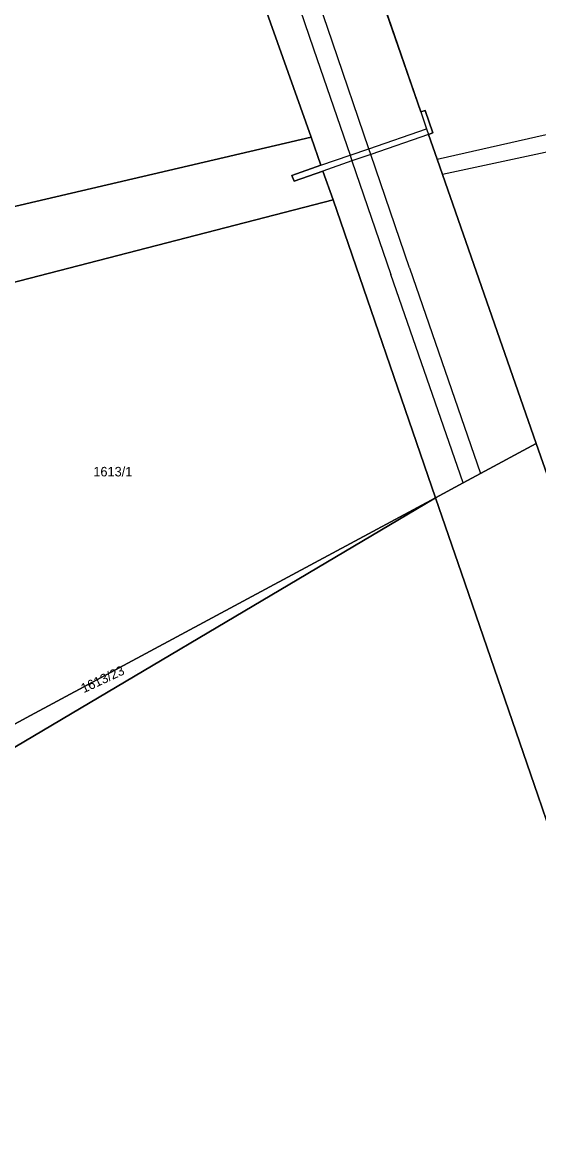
# Model space of a CAD drawing. Extents: x -263943 to -261149, y -1236934 to -1230686.
# Drawn here: x -262663.8 to -262555.5, y -1236658.9 to -1236424.4 of the extents above; entities that cross this region are included whole.
import ezdxf

# ---------------------------------------------------------------- set-up
doc = ezdxf.new("R2010")
doc.units = 0
for name, color, linetype in [('body_kn', 7, 'Continuous'), ('kladpar_druhypozemkov', 7, 'Continuous'), ('kladpar_hranice', 7, 'Continuous'), ('kladpar_parcelnecisla', 7, 'Continuous'), ('kladpar_plochy', 7, 'Continuous'), ('zappar_hrandruhpozemk', 7, 'Continuous'), ('zuob_linie', 7, 'Continuous'), ('zuob_plochy', 7, 'Continuous')]:
    doc.layers.add(name, color=color, linetype=linetype)

msp = doc.modelspace()

# ---------------------------------------------------------------- linework, layer by layer
at = {"layer": 'body_kn'}
for p, q in [((-262602.74, -1236429.99), (-262602.74, -1236429.99)), ((-262598.75, -1236428.57), (-262598.75, -1236428.57)), ((-262580.27, -1236443.22), (-262580.27, -1236443.22)), ((-262580.27, -1236443.22), (-262580.27, -1236443.22)), ((-262579.34, -1236442.89), (-262579.34, -1236442.89)), ((-262603.25, -1236448.52), (-262603.25, -1236448.52)), ((-262579.04, -1236446.74), (-262579.04, -1236446.74)), ((-262579.04, -1236446.74), (-262579.04, -1236446.74)), ((-262578.63, -1236447.93), (-262578.63, -1236447.93)), ((-262578.63, -1236447.93), (-262578.63, -1236447.93)), ((-262577.75, -1236447.63), (-262577.75, -1236447.63)), ((-262591.14, -1236450.94), (-262591.14, -1236450.94)), ((-262595.1, -1236452.31), (-262595.1, -1236452.31)), ((-262594.69, -1236453.5), (-262594.69, -1236453.5)), ((-262590.73, -1236452.13), (-262590.73, -1236452.13)), ((-262576.84, -1236453.1), (-262576.84, -1236453.1)), ((-262576.84, -1236453.1), (-262576.84, -1236453.1)), ((-262601.19, -1236454.42), (-262601.19, -1236454.42)), ((-262601.19, -1236454.42), (-262601.19, -1236454.42)), ((-262600.77, -1236455.61), (-262600.77, -1236455.61)), ((-262607.27, -1236456.53), (-262607.27, -1236456.53)), ((-262606.85, -1236457.72), (-262606.85, -1236457.72)), ((-262575.7, -1236456.35), (-262575.7, -1236456.35)), ((-262598.66, -1236461.66), (-262598.66, -1236461.66)), ((-262582.63, -1236475.95), (-262582.63, -1236475.95)), ((-262586.54, -1236477.29), (-262586.54, -1236477.29)), ((-262556.06, -1236512.78), (-262556.06, -1236512.78)), ((-262556.06, -1236512.78), (-262556.06, -1236512.78)), ((-262567.72, -1236519.05), (-262567.72, -1236519.05)), ((-262571.34, -1236520.99), (-262571.34, -1236520.99)), ((-262571.34, -1236520.99), (-262571.34, -1236520.99)), ((-262577.19, -1236524.13), (-262577.19, -1236524.13)), ((-262571.74, -1236539.97), (-262571.74, -1236539.97)), ((-262611.91, -1236542.78), (-262611.91, -1236542.78)), ((-262611.91, -1236542.78), (-262611.91, -1236542.78)), ((-262662.14, -1236569.78), (-262662.14, -1236569.78)), ((-262555.72, -1236586.53), (-262555.72, -1236586.53))]:
    msp.add_line(p, q, dxfattribs=at)
at = {"layer": 'kladpar_druhypozemkov'}
for p, q in [((-262644.48, -1236517.35), (-262644.48, -1236517.35)), ((-262640.16, -1236560.26), (-262640.16, -1236560.26))]:
    msp.add_line(p, q, dxfattribs=at)
at = {"layer": 'kladpar_hranice'}
msp.add_line((-262555.72, -1236586.53), (-262539.77, -1236633.03), dxfattribs=at)
for points in [[(-262642.35, -1236338.08), (-262623.64, -1236391.05), (-262603.25, -1236448.52), (-262686.84, -1236468.05), (-262780.06, -1236489.47), (-262796.24, -1236388.03), (-262804.88, -1236333.48), (-262777.92, -1236327.98), (-262779.92, -1236319.26), (-262779.84, -1236319.6), (-262664.48, -1236274.71), (-262659.55, -1236288.77), (-262642.35, -1236338.08)], [(-262601.19, -1236454.42), (-262607.27, -1236456.53), (-262606.85, -1236457.72), (-262600.77, -1236455.61), (-262598.66, -1236461.66), (-262695.31, -1236486.62), (-262780.6, -1236508.3), (-262783.02, -1236489.29), (-262789.43, -1236449.74), (-262794.77, -1236417.14), (-262798.53, -1236388.86), (-262803.35, -1236353.48), (-262806.22, -1236333.75), (-262804.88, -1236333.48), (-262796.24, -1236388.03), (-262780.06, -1236489.47), (-262686.84, -1236468.05), (-262603.25, -1236448.52), (-262601.19, -1236454.42)], [(-262593.33, -1236405.21), (-262580.27, -1236443.22), (-262579.34, -1236442.89), (-262577.75, -1236447.63), (-262578.63, -1236447.93), (-262576.84, -1236453.1), (-262575.7, -1236456.35), (-262556.06, -1236512.78), (-262567.72, -1236519.05), (-262571.34, -1236520.99), (-262577.19, -1236524.13), (-262598.66, -1236461.66), (-262600.77, -1236455.61), (-262606.85, -1236457.72), (-262607.27, -1236456.53), (-262601.19, -1236454.42), (-262603.25, -1236448.52), (-262623.64, -1236391.05)], [(-262524.46, -1236447.57), (-262521.3, -1236458.84), (-262514.56, -1236483.59), (-262509.72, -1236512.7), (-262499.2, -1236547.9), (-262502.43, -1236548.99), (-262502.1, -1236550), (-262507.62, -1236551.91), (-262500.4, -1236573.67), (-262498.7, -1236573.09), (-262500.98, -1236566.45), (-262494.28, -1236564.34), (-262483.29, -1236593.94), (-262522.82, -1236607.43), (-262556.06, -1236512.78), (-262575.7, -1236456.35), (-262576.84, -1236453.1), (-262578.63, -1236447.93), (-262577.75, -1236447.63), (-262579.34, -1236442.89), (-262580.27, -1236443.22), (-262593.33, -1236405.21)], [(-262611.91, -1236542.78), (-262662.14, -1236569.78), (-262683.46, -1236581.32), (-262696.75, -1236507.43), (-262776.75, -1236524.51), (-262761.06, -1236623.74), (-262766.17, -1236626.53), (-262770.84, -1236597.6), (-262775.67, -1236557.81), (-262778.48, -1236533.64), (-262779.42, -1236522.66), (-262780.6, -1236508.3), (-262695.31, -1236486.62), (-262598.66, -1236461.66), (-262577.19, -1236524.13), (-262611.91, -1236542.78)], [(-262479.88, -1236730.93), (-262475.21, -1236744.92), (-262469.95, -1236759.68), (-262458.91, -1236784.95), (-262446.54, -1236794.37), (-262466.36, -1236804.28), (-262469.83, -1236806.02), (-262480.66, -1236811.44), (-262483.04, -1236804.12), (-262486.95, -1236786.65), (-262523.57, -1236680.3), (-262539.77, -1236633.03), (-262555.72, -1236586.53), (-262571.74, -1236539.97), (-262577.19, -1236524.13), (-262571.34, -1236520.99), (-262567.72, -1236519.05), (-262556.06, -1236512.78), (-262522.82, -1236607.43), (-262510.86, -1236641.99), (-262495.65, -1236686.15), (-262479.88, -1236730.93)], [(-262739.04, -1236788.7), (-262744.54, -1236755.96), (-262752.57, -1236708.7), (-262757.39, -1236680.53), (-262762.61, -1236649.27), (-262765.1, -1236633.35), (-262760, -1236630.45), (-262695.89, -1236594.1), (-262684.11, -1236588.74), (-262684.27, -1236587.51), (-262682.52, -1236586.52), (-262577.19, -1236524.13), (-262571.74, -1236539.97), (-262555.72, -1236586.53)], [(-262682.52, -1236586.52), (-262683.46, -1236581.32), (-262662.14, -1236569.78), (-262611.91, -1236542.78), (-262577.19, -1236524.13), (-262682.52, -1236586.52)]]:
    msp.add_lwpolyline(points, dxfattribs=at)
at = {"layer": 'kladpar_plochy'}
for p, q in [((-262580.27, -1236443.22), (-262593.33, -1236405.21)), ((-262579.34, -1236442.89), (-262580.27, -1236443.22)), ((-262577.75, -1236447.63), (-262579.34, -1236442.89)), ((-262578.63, -1236447.93), (-262577.75, -1236447.63)), ((-262576.84, -1236453.1), (-262578.63, -1236447.93)), ((-262575.7, -1236456.35), (-262576.84, -1236453.1)), ((-262556.06, -1236512.78), (-262575.7, -1236456.35)), ((-262522.82, -1236607.43), (-262556.06, -1236512.78)), ((-262682.52, -1236586.52), (-262577.19, -1236524.13)), ((-262577.19, -1236524.13), (-262571.74, -1236539.97)), ((-262571.74, -1236539.97), (-262555.72, -1236586.53)), ((-262555.72, -1236586.53), (-262539.77, -1236633.03))]:
    msp.add_line(p, q, dxfattribs=at)
for points in [[(-262642.35, -1236338.08), (-262623.64, -1236391.05), (-262603.25, -1236448.52), (-262686.84, -1236468.05), (-262780.06, -1236489.47), (-262796.24, -1236388.03), (-262804.88, -1236333.48), (-262777.92, -1236327.98), (-262779.92, -1236319.26), (-262779.84, -1236319.6), (-262664.48, -1236274.71), (-262659.55, -1236288.77)], [(-262601.19, -1236454.42), (-262607.27, -1236456.53), (-262606.85, -1236457.72), (-262600.77, -1236455.61), (-262598.66, -1236461.66), (-262695.31, -1236486.62), (-262780.6, -1236508.3), (-262783.02, -1236489.29), (-262789.43, -1236449.74), (-262794.77, -1236417.14), (-262798.53, -1236388.86), (-262803.35, -1236353.48), (-262806.22, -1236333.75), (-262804.88, -1236333.48), (-262796.24, -1236388.03), (-262780.06, -1236489.47), (-262686.84, -1236468.05), (-262603.25, -1236448.52)], [(-262611.91, -1236542.78), (-262662.14, -1236569.78), (-262683.46, -1236581.32), (-262696.75, -1236507.43), (-262776.75, -1236524.51), (-262761.06, -1236623.74), (-262766.17, -1236626.53), (-262770.84, -1236597.6), (-262775.67, -1236557.81), (-262778.48, -1236533.64), (-262779.42, -1236522.66), (-262780.6, -1236508.3), (-262695.31, -1236486.62), (-262598.66, -1236461.66), (-262577.19, -1236524.13)], [(-262479.88, -1236730.93), (-262475.21, -1236744.92), (-262469.95, -1236759.68), (-262458.91, -1236784.95), (-262446.54, -1236794.37), (-262466.36, -1236804.28), (-262469.83, -1236806.02), (-262480.66, -1236811.44), (-262483.04, -1236804.12), (-262486.95, -1236786.65), (-262523.57, -1236680.3), (-262539.77, -1236633.03), (-262555.72, -1236586.53), (-262571.74, -1236539.97), (-262577.19, -1236524.13), (-262571.34, -1236520.99), (-262567.72, -1236519.05), (-262556.06, -1236512.78), (-262522.82, -1236607.43), (-262510.86, -1236641.99), (-262495.65, -1236686.15)], [(-262682.52, -1236586.52), (-262683.46, -1236581.32), (-262662.14, -1236569.78), (-262611.91, -1236542.78), (-262577.19, -1236524.13)]]:
    msp.add_lwpolyline(points, close=True, dxfattribs=at)
msp.add_lwpolyline([(-262593.33, -1236405.21), (-262580.27, -1236443.22), (-262579.34, -1236442.89), (-262577.75, -1236447.63), (-262578.63, -1236447.93), (-262576.84, -1236453.1), (-262575.7, -1236456.35), (-262556.06, -1236512.78), (-262567.72, -1236519.05), (-262571.34, -1236520.99), (-262577.19, -1236524.13), (-262598.66, -1236461.66), (-262600.77, -1236455.61), (-262606.85, -1236457.72), (-262607.27, -1236456.53), (-262601.19, -1236454.42), (-262603.25, -1236448.52), (-262623.64, -1236391.05)], dxfattribs=at)
at = {"layer": 'zappar_hrandruhpozemk'}
for p, q in [((-262580.27, -1236443.22), (-262579.04, -1236446.74)), ((-262576.84, -1236453.1), (-262539.75, -1236444.79)), ((-262579.04, -1236446.74), (-262578.63, -1236447.93)), ((-262538.9, -1236448.4), (-262575.7, -1236456.35)), ((-262582.63, -1236475.95), (-262567.72, -1236519.05)), ((-262571.34, -1236520.99), (-262586.54, -1236477.29))]:
    msp.add_line(p, q, dxfattribs=at)
for points in [[(-262618.85, -1236382.87), (-262602.74, -1236429.99), (-262595.1, -1236452.31), (-262594.69, -1236453.5), (-262586.54, -1236477.29)], [(-262582.63, -1236475.95), (-262590.73, -1236452.13), (-262591.14, -1236450.94), (-262598.75, -1236428.57), (-262614.87, -1236381.45)], [(-262601.19, -1236454.42), (-262595.1, -1236452.31), (-262591.14, -1236450.94), (-262579.04, -1236446.74)], [(-262578.63, -1236447.93), (-262590.73, -1236452.13), (-262594.69, -1236453.5), (-262600.77, -1236455.61)]]:
    msp.add_lwpolyline(points, dxfattribs=at)
at = {"layer": 'zuob_linie'}
for points in [[(-262699.7, -1236119.81), (-262681.18, -1236174.94), (-262664.48, -1236207.15), (-262639.91, -1236238.48), (-262648, -1236246.64), (-262648.54, -1236254.07), (-262634.5, -1236291.78), (-262630.9, -1236300.68), (-262620.62, -1236329.06), (-262608.06, -1236366.25), (-262593.33, -1236405.21), (-262580.27, -1236443.22), (-262579.34, -1236442.89), (-262577.75, -1236447.63), (-262578.63, -1236447.93), (-262576.84, -1236453.1), (-262575.7, -1236456.35), (-262556.06, -1236512.78), (-262522.82, -1236607.43), (-262510.86, -1236641.99), (-262495.65, -1236686.15)], [(-262556.06, -1236512.78), (-262575.7, -1236456.35), (-262576.84, -1236453.1), (-262578.63, -1236447.93), (-262577.75, -1236447.63), (-262579.34, -1236442.89), (-262580.27, -1236443.22), (-262593.33, -1236405.21), (-262608.06, -1236366.25), (-262620.62, -1236329.06), (-262630.9, -1236300.68), (-262634.5, -1236291.78), (-262648.54, -1236254.07), (-262648, -1236246.64), (-262639.91, -1236238.48), (-262664.48, -1236207.15), (-262681.18, -1236174.94), (-262699.7, -1236119.81)], [(-262495.65, -1236686.15), (-262510.86, -1236641.99), (-262522.82, -1236607.43), (-262556.06, -1236512.78)]]:
    msp.add_lwpolyline(points, dxfattribs=at)
at = {"layer": 'zuob_plochy'}
for points in [[(-262699.7, -1236119.81), (-262681.18, -1236174.94), (-262664.48, -1236207.15), (-262639.91, -1236238.48), (-262648, -1236246.64), (-262648.54, -1236254.07), (-262634.5, -1236291.78), (-262630.9, -1236300.68), (-262620.62, -1236329.06), (-262608.06, -1236366.25), (-262593.33, -1236405.21), (-262580.27, -1236443.22), (-262579.34, -1236442.89), (-262577.75, -1236447.63), (-262578.63, -1236447.93), (-262576.84, -1236453.1), (-262575.7, -1236456.35), (-262556.06, -1236512.78), (-262522.82, -1236607.43), (-262510.86, -1236641.99), (-262495.65, -1236686.15)], [(-262495.65, -1236686.15), (-262510.86, -1236641.99), (-262522.82, -1236607.43), (-262556.06, -1236512.78), (-262575.7, -1236456.35), (-262576.84, -1236453.1), (-262578.63, -1236447.93), (-262577.75, -1236447.63), (-262579.34, -1236442.89), (-262580.27, -1236443.22), (-262593.33, -1236405.21), (-262608.06, -1236366.25), (-262620.62, -1236329.06), (-262630.9, -1236300.68), (-262634.5, -1236291.78), (-262648.54, -1236254.07), (-262648, -1236246.64), (-262639.91, -1236238.48), (-262664.48, -1236207.15), (-262681.18, -1236174.94), (-262699.7, -1236119.81)]]:
    msp.add_lwpolyline(points, dxfattribs=at)

# ---------------------------------------------------------------- texts
at = {"layer": 'kladpar_parcelnecisla'}
for s, rotation, p in [('1613/1', 360, (-262648.95, -1236519.66)), ('1613/23', 25, (-262650.98, -1236565.14))]:
    msp.add_text(s, height=2, rotation=rotation, dxfattribs=at).set_placement(p)

doc.saveas('drawing.dxf')
